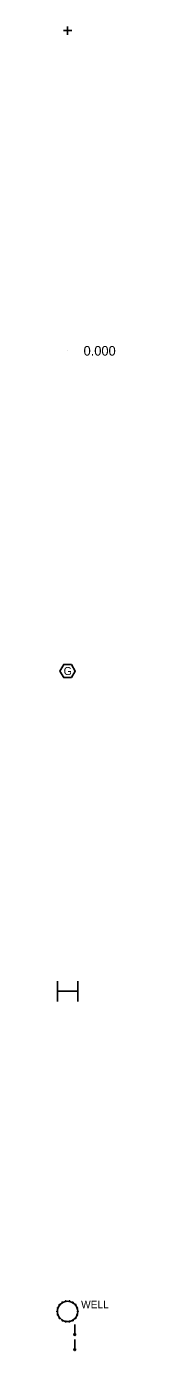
# Model space of a CAD drawing. Extents: x 98 to 2902, y -6 to 903.
# Drawn here: x 898.3 to 907.4, y 243.9 to 450.6 of the extents above; entities that cross this region are included whole.
import ezdxf

# ---------------------------------------------------------------- set-up
doc = ezdxf.new("R2010")
doc.units = 0
for name, color, linetype in [('V-FUEL-DEVC', 7, 'Continuous'), ('V-FUEL-METR', 7, 'Continuous'), ('V-LITE-EXTR', 7, 'Continuous'), ('V-SITE-FENC', 7, 'Continuous'), ('V-TOPO-SPOT', 7, 'Continuous')]:
    doc.layers.add(name, color=color, linetype=linetype)

msp = doc.modelspace()

# ---------------------------------------------------------------- linework, layer by layer
at = {"layer": 'V-FUEL-DEVC'}
for p, q in [((898.48, 250.55), (898.48, 250.55)), ((898.76, 251.04), (898.76, 251.04)), ((899.19, 251.4), (899.19, 251.4)), ((899.72, 251.59), (899.72, 251.59)), ((900.28, 251.59), (900.28, 251.59)), ((900.81, 251.4), (900.81, 251.4)), ((901.24, 251.04), (901.24, 251.04)), ((901.52, 250.55), (901.52, 250.55)), ((898.39, 250), (898.39, 250)), ((898.48, 249.45), (898.48, 249.45)), ((898.76, 248.96), (898.76, 248.96)), ((899.19, 248.6), (899.19, 248.6)), ((899.72, 248.41), (899.72, 248.41)), ((900.28, 248.41), (900.28, 248.41)), ((900.81, 248.6), (900.81, 248.6)), ((901.24, 248.96), (901.24, 248.96)), ((901.52, 249.45), (901.52, 249.45)), ((901.61, 250), (901.61, 250)), ((901.12, 247.98), (901.12, 246.55)), ((901.12, 245.62), (901.12, 244.19))]:
    msp.add_line(p, q, dxfattribs=at)
for centre, radius in [((900, 250), 1.59), ((898.48, 250.55), 0.0717), ((898.76, 251.04), 0.0717), ((899.19, 251.4), 0.0717), ((899.72, 251.59), 0.0717), ((900.28, 251.59), 0.0717), ((900.81, 251.4), 0.0717), ((901.24, 251.04), 0.0717), ((901.52, 250.55), 0.0717), ((898.39, 250), 0.0717), ((898.48, 249.45), 0.0717), ((898.76, 248.96), 0.0717), ((899.19, 248.6), 0.0717), ((899.72, 248.41), 0.0717), ((900.28, 248.41), 0.0717), ((900.81, 248.6), 0.0717), ((901.24, 248.96), 0.0717), ((901.52, 249.45), 0.0717), ((901.61, 250), 0.0717), ((901.12, 246.41), 0.143), ((901.12, 244.04), 0.143)]:
    msp.add_circle(centre, radius, dxfattribs=at)
at = {"layer": 'V-FUEL-METR'}
msp.add_lwpolyline([(900.6, 348.97), (901.19, 350), (900.6, 351.03), (899.4, 351.03), (898.81, 350), (899.4, 348.97)], close=True, dxfattribs=at)
at = {"layer": 'V-LITE-EXTR'}
for p, q in [((900, 450), (899.35, 450)), ((900, 450.65), (900, 449.35)), ((900, 450), (900.65, 450))]:
    msp.add_line(p, q, dxfattribs=at)
at = {"layer": 'V-SITE-FENC'}
for p, q in [((898.41, 298.41), (898.41, 301.59)), ((898.41, 300), (901.59, 300)), ((901.59, 298.41), (901.59, 301.59))]:
    msp.add_line(p, q, dxfattribs=at)
at = {"layer": 'V-TOPO-SPOT'}
msp.add_line((900, 400), (900, 400), dxfattribs=at)

# ---------------------------------------------------------------- texts
at = {"layer": 'V-FUEL-DEVC'}
msp.add_text('WELL', height=1.189, dxfattribs=at).set_placement((902.11, 250.49))
at = {"layer": 'V-FUEL-METR'}
msp.add_text('G', height=1.25, dxfattribs=at).set_placement((899.38, 349.38))
at = {"layer": 'V-TOPO-SPOT'}
msp.add_text('0.000', height=1.5, dxfattribs=at).set_placement((902.5, 399.25))

doc.saveas('drawing.dxf')
